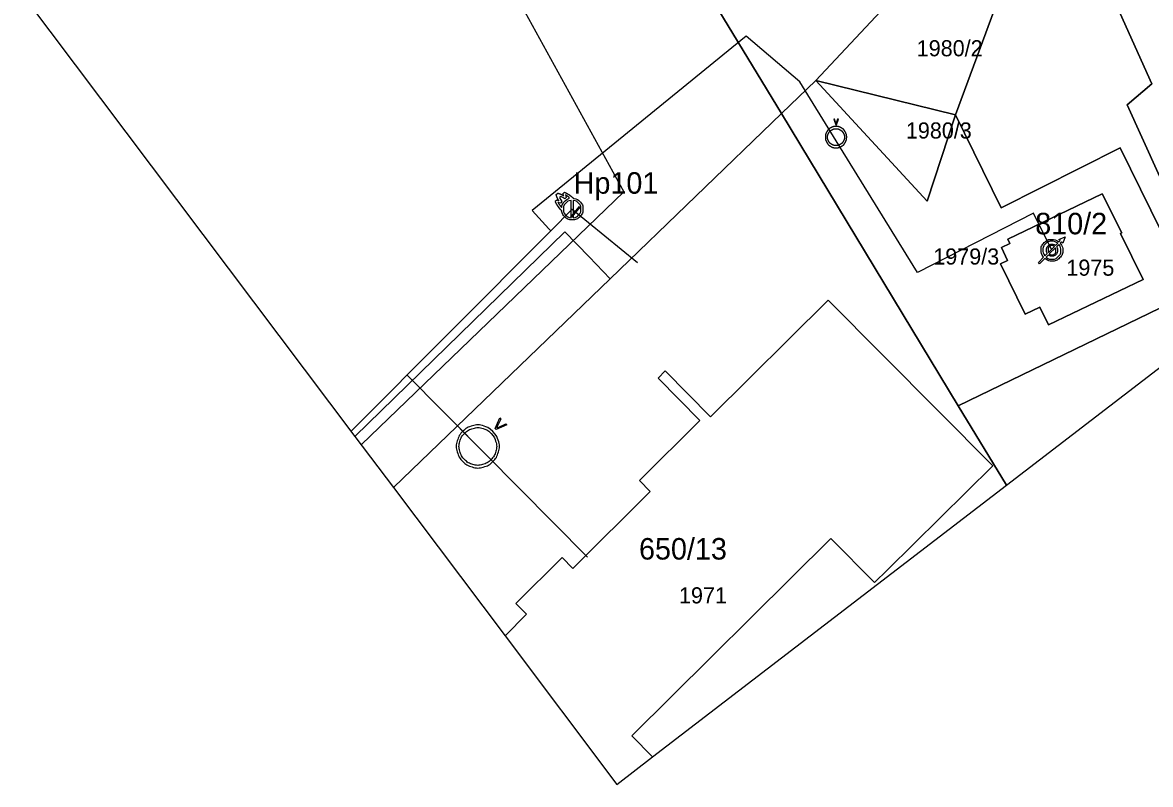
# Model space of a CAD drawing. Extents: x -570698 to -570232, y -1086952 to -1086596.
# Drawn here: x -570538 to -570433, y -1086951.6 to -1086880.7 of the extents above; entities that cross this region are included whole.
import ezdxf

# ---------------------------------------------------------------- set-up
doc = ezdxf.new("R2010")
doc.units = 0
for name, color, linetype in [('Adresní místo-text', 7, 'Continuous'), ('Armatura vodovodní', 7, 'Continuous'), ('Default', 7, 'Continuous'), ('Hydrant', 7, 'Continuous'), ('Kanalizační stoka', 7, 'Continuous'), ('Odběrné místo', 7, 'Continuous'), ('Označení hydrantu', 7, 'Continuous'), ('Parcela-polygon', 7, 'Continuous'), ('Parcela-text', 7, 'Continuous'), ('Vodovodní přípojka', 7, 'Continuous'), ('Vodovodní řad', 7, 'Continuous'), ('Vodovodní šachta', 7, 'Continuous')]:
    doc.layers.add(name, color=color, linetype=linetype)

msp = doc.modelspace()

# ---------------------------------------------------------------- linework, layer by layer
at = {"layer": 'Armatura vodovodní'}
msp.add_lwpolyline([(-570486.13, -1086897.88), (-570486.92, -1086898.84), (-570486.99, -1086898.79), (-570486.19, -1086897.83), (-570486.13, -1086897.88)], dxfattribs=at)
at = {"layer": 'Default'}
for points, degree in [([(-570463.17, -1086890.89), (-570463.26, -1086891.05), (-570463.3, -1086891.22), (-570463.3, -1086891.39)], 2), ([(-570462.8, -1086890.53), (-570462.96, -1086890.61), (-570463.08, -1086890.73), (-570463.17, -1086890.89)], 2), ([(-570463.1, -1086891.39), (-570463.1, -1086891.26), (-570463.06, -1086891.13), (-570462.99, -1086891)], 2), ([(-570462.99, -1086891), (-570462.92, -1086890.88), (-570462.82, -1086890.78), (-570462.7, -1086890.71)], 2), ([(-570462.32, -1086890.4), (-570462.48, -1086890.4), (-570462.64, -1086890.44), (-570462.8, -1086890.53)], 2), ([(-570462.7, -1086890.71), (-570462.57, -1086890.64), (-570462.45, -1086890.61), (-570462.32, -1086890.61)], 2), ([(-570462.31, -1086890.13), (-570462.31, -1086890.11), (-570462.31, -1086890.1), (-570462.32, -1086890.09)], 2), ([(-570461.83, -1086890.53), (-570461.99, -1086890.44), (-570462.15, -1086890.4), (-570462.32, -1086890.4)], 2), ([(-570462.32, -1086890.61), (-570462.18, -1086890.61), (-570462.06, -1086890.64), (-570461.93, -1086890.71)], 2), ([(-570462.29, -1086890.09), (-570462.3, -1086890.1), (-570462.3, -1086890.11), (-570462.31, -1086890.13)], 2), ([(-570461.93, -1086890.71), (-570461.81, -1086890.78), (-570461.71, -1086890.88), (-570461.64, -1086891)], 2), ([(-570461.46, -1086890.89), (-570461.55, -1086890.73), (-570461.67, -1086890.61), (-570461.83, -1086890.53)], 2), ([(-570461.64, -1086891), (-570461.57, -1086891.13), (-570461.53, -1086891.26), (-570461.53, -1086891.39)], 2), ([(-570461.32, -1086891.39), (-570461.32, -1086891.22), (-570461.37, -1086891.05), (-570461.46, -1086890.89)], 2), ([(-570463.3, -1086891.39), (-570463.3, -1086891.56), (-570463.26, -1086891.73), (-570463.17, -1086891.88)], 2), ([(-570463.17, -1086891.88), (-570463.08, -1086892.04), (-570462.96, -1086892.16), (-570462.8, -1086892.25)], 2), ([(-570462.99, -1086891.78), (-570463.06, -1086891.66), (-570463.1, -1086891.53), (-570463.1, -1086891.39)], 2), ([(-570462.7, -1086892.07), (-570462.82, -1086892), (-570462.92, -1086891.9), (-570462.99, -1086891.78)], 2), ([(-570461.64, -1086891.78), (-570461.71, -1086891.9), (-570461.8, -1086892), (-570461.93, -1086892.07)], 2), ([(-570461.82, -1086892.25), (-570461.66, -1086892.16), (-570461.54, -1086892.04), (-570461.45, -1086891.88)], 2), ([(-570461.53, -1086891.39), (-570461.53, -1086891.53), (-570461.57, -1086891.66), (-570461.64, -1086891.78)], 2), ([(-570461.45, -1086891.88), (-570461.37, -1086891.73), (-570461.32, -1086891.56), (-570461.32, -1086891.39)], 2), ([(-570462.8, -1086892.25), (-570462.65, -1086892.34), (-570462.48, -1086892.38), (-570462.32, -1086892.38)], 2), ([(-570462.32, -1086892.17), (-570462.45, -1086892.17), (-570462.58, -1086892.14), (-570462.7, -1086892.07)], 2), ([(-570461.93, -1086892.07), (-570462.05, -1086892.14), (-570462.18, -1086892.17), (-570462.32, -1086892.17)], 2), ([(-570462.32, -1086892.38), (-570462.14, -1086892.38), (-570461.98, -1086892.34), (-570461.82, -1086892.25)], 2), ([(-570488.11, -1086897.3), (-570488.28, -1086897.03), (-570488.36, -1086896.74)], 2), ([(-570488.21, -1086896.6), (-570487.93, -1086896.67), (-570487.65, -1086896.84)], 2), ([(-570487.56, -1086897.13), (-570487.81, -1086896.94), (-570488.1, -1086896.85), (-570488.01, -1086897.14), (-570487.82, -1086897.39)], 3), ([(-570486.73, -1086897.09), (-570486.41, -1086897.13), (-570486.16, -1086897.37), (-570485.87, -1086897.67), (-570485.87, -1086898.08), (-570485.87, -1086898.49), (-570486.16, -1086898.79), (-570486.45, -1086899.08), (-570486.87, -1086899.08), (-570487.28, -1086899.08), (-570487.57, -1086898.79), (-570487.82, -1086898.55), (-570487.86, -1086898.22)], 3), ([(-570486.96, -1086897.27), (-570487.24, -1086897.3), (-570487.45, -1086897.51), (-570487.69, -1086897.75), (-570487.68, -1086898.08), (-570487.68, -1086898.42), (-570487.44, -1086898.66), (-570487.24, -1086898.86), (-570486.96, -1086898.89)], 3), ([(-570487.59, -1086896.51), (-570487.33, -1086896.63), (-570487.1, -1086896.78)], 2), ([(-570487.51, -1086897.31), (-570487.29, -1086897.13), (-570487.02, -1086897.09), (-570487.24, -1086896.91), (-570487.48, -1086896.77)], 3), ([(-570486.84, -1086896.99), (-570486.83, -1086897), (-570486.73, -1086897.09)], 2), ([(-570486.77, -1086898.89), (-570486.5, -1086898.86), (-570486.3, -1086898.65), (-570486.06, -1086898.42), (-570486.06, -1086898.08), (-570486.06, -1086897.74), (-570486.3, -1086897.51), (-570486.5, -1086897.3), (-570486.78, -1086897.27)], 3), ([(-570488.17, -1086897.85), (-570488.32, -1086897.63), (-570488.44, -1086897.36)], 2), ([(-570488.19, -1086897.47), (-570488.04, -1086897.72), (-570487.86, -1086897.93)], 2), ([(-570487.86, -1086898.26), (-570487.86, -1086898.24), (-570487.87, -1086898.22), (-570487.97, -1086898.1), (-570488.05, -1086898.01)], 3), ([(-570487.86, -1086897.93), (-570487.82, -1086897.66), (-570487.64, -1086897.44)], 2), ([(-570442.99, -1086902.56), (-570443.23, -1086902.29), (-570443.23, -1086901.91), (-570443.23, -1086901.49), (-570442.93, -1086901.2), (-570442.64, -1086900.9), (-570442.22, -1086900.9), (-570441.84, -1086900.9), (-570441.57, -1086901.14)], 3), ([(-570441.68, -1086901.26), (-570441.91, -1086901.07), (-570442.22, -1086901.07), (-570442.57, -1086901.07), (-570442.81, -1086901.32), (-570443.06, -1086901.56), (-570443.06, -1086901.91), (-570443.06, -1086902.22), (-570442.87, -1086902.44)], 3), ([(-570441.46, -1086901.25), (-570441.21, -1086901.53), (-570441.21, -1086901.91), (-570441.21, -1086902.33), (-570441.5, -1086902.62), (-570441.8, -1086902.92), (-570442.22, -1086902.92), (-570442.6, -1086902.92), (-570442.88, -1086902.67)], 3), ([(-570442.76, -1086902.55), (-570442.53, -1086902.75), (-570442.22, -1086902.75), (-570441.87, -1086902.75), (-570441.62, -1086902.5), (-570441.38, -1086902.26), (-570441.38, -1086901.91), (-570441.38, -1086901.6), (-570441.58, -1086901.37)], 3), ([(-570442.65, -1086902.22), (-570442.65, -1086902.21), (-570442.66, -1086902.19), (-570442.72, -1086902.07), (-570442.72, -1086901.92), (-570442.72, -1086901.66), (-570442.58, -1086901.5), (-570442.44, -1086901.35), (-570442.21, -1086901.35), (-570442.06, -1086901.35), (-570441.94, -1086901.42), (-570441.91, -1086901.44), (-570441.89, -1086901.46)], 3), ([(-570441.98, -1086901.56), (-570442, -1086901.54), (-570442.02, -1086901.53), (-570442.1, -1086901.48), (-570442.21, -1086901.48), (-570442.36, -1086901.48), (-570442.47, -1086901.58), (-570442.58, -1086901.68), (-570442.58, -1086901.93), (-570442.58, -1086902.04), (-570442.54, -1086902.12)], 3), ([(-570441.79, -1086901.58), (-570441.77, -1086901.6), (-570441.76, -1086901.62), (-570441.7, -1086901.75), (-570441.7, -1086901.91), (-570441.7, -1086902.07), (-570441.76, -1086902.2), (-570441.83, -1086902.33), (-570441.95, -1086902.4), (-570442.07, -1086902.47), (-570442.21, -1086902.47), (-570442.36, -1086902.47), (-570442.48, -1086902.39), (-570442.52, -1086902.37), (-570442.55, -1086902.34)], 3), ([(-570442.46, -1086902.25), (-570442.36, -1086902.34), (-570442.21, -1086902.34), (-570442.05, -1086902.34), (-570441.95, -1086902.23), (-570441.84, -1086902.12), (-570441.84, -1086901.91), (-570441.84, -1086901.78), (-570441.89, -1086901.68), (-570441.89, -1086901.68), (-570441.89, -1086901.68)], 3), ([(-570494.25, -1086918.76), (-570493.89, -1086919.12), (-570493.74, -1086919.63), (-570493.59, -1086920.15), (-570493.74, -1086920.67), (-570493.89, -1086921.2), (-570494.26, -1086921.57), (-570494.62, -1086921.93), (-570495.14, -1086922.07), (-570495.66, -1086922.22), (-570496.17, -1086922.07), (-570496.69, -1086921.92), (-570497.06, -1086921.55), (-570497.41, -1086921.19), (-570497.56, -1086920.67), (-570497.71, -1086920.15), (-570497.56, -1086919.63), (-570497.41, -1086919.12), (-570497.04, -1086918.75), (-570496.68, -1086918.39), (-570496.15, -1086918.24), (-570495.63, -1086918.09), (-570495.11, -1086918.25), (-570494.6, -1086918.41), (-570494.25, -1086918.76)], 3), ([(-570494.42, -1086918.94), (-570494.73, -1086918.63), (-570495.18, -1086918.49), (-570495.63, -1086918.35), (-570496.09, -1086918.48), (-570496.55, -1086918.61), (-570496.87, -1086918.93), (-570497.19, -1086919.25), (-570497.32, -1086919.7), (-570497.45, -1086920.15), (-570497.32, -1086920.6), (-570497.2, -1086921.06), (-570496.88, -1086921.38), (-570496.56, -1086921.7), (-570496.11, -1086921.83), (-570495.66, -1086921.96), (-570495.2, -1086921.83), (-570494.75, -1086921.71), (-570494.43, -1086921.39), (-570494.11, -1086921.07), (-570493.98, -1086920.61), (-570493.85, -1086920.15), (-570493.98, -1086919.7), (-570494.11, -1086919.25), (-570494.42, -1086918.94)], 3), ([(-570493.84, -1086918.31), (-570493.88, -1086918.4), (-570493.92, -1086918.46), (-570493.84, -1086918.42), (-570493.76, -1086918.39)], 3)]:
    msp.add_open_spline(points, degree=degree, dxfattribs=at)
at = {"layer": 'Hydrant'}
for points in [[(-570488.44, -1086897.36), (-570488.3, -1086897.22), (-570488.11, -1086897.3)], [(-570488.36, -1086896.74), (-570488.21, -1086896.6)], [(-570487.65, -1086896.84), (-570487.73, -1086896.66), (-570487.59, -1086896.51)], [(-570487.48, -1086896.77), (-570487.42, -1086896.99), (-570487.56, -1086897.13)], [(-570487.1, -1086896.78), (-570486.94, -1086896.91), (-570486.84, -1086896.99)], [(-570486.96, -1086898.89), (-570486.96, -1086897.27)], [(-570486.78, -1086897.27), (-570486.77, -1086898.89)], [(-570487.82, -1086897.39), (-570487.96, -1086897.54), (-570488.19, -1086897.47)], [(-570488.05, -1086898.01), (-570488.17, -1086897.85)], [(-570487.86, -1086898.22), (-570487.86, -1086898.26)], [(-570487.64, -1086897.44), (-570487.51, -1086897.31)]]:
    msp.add_lwpolyline(points, dxfattribs=at)
at = {"layer": 'Kanalizační stoka'}
msp.add_lwpolyline([(-570457.86, -1086836.16), (-570493.65, -1086875.35), (-570482.06, -1086896.49), (-570506.5, -1086920.01)], dxfattribs=at)
at = {"layer": 'Odběrné místo'}
for points in [[(-570441.89, -1086901.46), (-570441.68, -1086901.26)], [(-570441.58, -1086901.37), (-570441.79, -1086901.58)], [(-570441.57, -1086901.14), (-570441.44, -1086901.01)], [(-570441.44, -1086901.01), (-570441.56, -1086900.9), (-570440.97, -1086900.66), (-570441.19, -1086901.25), (-570441.33, -1086901.12), (-570441.46, -1086901.25)], [(-570442.87, -1086902.44), (-570442.65, -1086902.22)], [(-570442.55, -1086902.34), (-570442.76, -1086902.55)], [(-570442.54, -1086902.12), (-570441.98, -1086901.56)], [(-570441.89, -1086901.68), (-570442.46, -1086902.25)], [(-570442.88, -1086902.67), (-570443.37, -1086903.16), (-570443.47, -1086903.05), (-570442.99, -1086902.56)]]:
    msp.add_lwpolyline(points, dxfattribs=at)
at = {"layer": 'Parcela-polygon'}
for p, q in [((-570538.02, -1086878.14), (-570507.09, -1086919.23)), ((-570446.46, -1086923.76), (-570427.79, -1086909.43)), ((-570507.09, -1086919.23), (-570503.51, -1086923.98)), ((-570503.51, -1086923.98), (-570493.12, -1086937.77)), ((-570479.39, -1086949.04), (-570446.46, -1086923.76))]:
    msp.add_line(p, q, dxfattribs=at)
for points in [[(-570314.47, -1086822.42), (-570326.4, -1086786.46), (-570358.49, -1086797.03), (-570369.36, -1086800.59), (-570374.8, -1086803.82), (-570380.97, -1086807.48), (-570374.82, -1086826.12), (-570380.47, -1086828.04), (-570398.24, -1086834.1), (-570397.51, -1086836.02), (-570406.58, -1086839.09), (-570441.99, -1086865.7), (-570438.81, -1086873.31), (-570432.93, -1086886.42), (-570435.2, -1086888.38), (-570429.44, -1086901.1), (-570427.79, -1086909.43)], [(-570507.09, -1086919.23), (-570487.55, -1086900.19), (-570485.3, -1086902.53), (-570483.34, -1086904.56), (-570467.38, -1086889.2), (-570492.56, -1086847.83), (-570501.11, -1086855.03), (-570507, -1086859.73), (-570511.23, -1086862.75), (-570515.08, -1086865.32), (-570518.55, -1086867.44), (-570522.04, -1086869.52), (-570526.69, -1086872.16), (-570538.02, -1086878.14)], [(-570427.79, -1086909.43), (-570429.44, -1086901.1), (-570435.2, -1086888.38), (-570432.93, -1086886.42), (-570438.81, -1086873.31), (-570441.99, -1086865.7), (-570442.31, -1086864.93), (-570447.84, -1086880.26), (-570451.19, -1086889.31), (-570446.95, -1086897.96), (-570435.85, -1086892.39), (-570429.23, -1086905.88), (-570450.94, -1086916.37), (-570446.46, -1086923.76)], [(-570446.46, -1086923.76), (-570450.94, -1086916.37), (-570467.38, -1086889.2), (-570483.34, -1086904.56), (-570503.51, -1086923.98)], [(-570503.51, -1086923.98), (-570483.34, -1086904.56), (-570485.3, -1086902.53), (-570487.55, -1086900.19), (-570507.09, -1086919.23)], [(-570493.12, -1086937.77), (-570491.11, -1086935.77), (-570492.11, -1086934.77), (-570487.81, -1086930.49), (-570486.8, -1086931.5), (-570479.6, -1086924.35), (-570480.6, -1086923.34), (-570474.98, -1086917.75), (-570478.88, -1086913.81), (-570478.2, -1086913.14), (-570473.98, -1086917.41), (-570463.03, -1086906.56), (-570447.71, -1086921.95), (-570457.53, -1086931.62), (-570458.74, -1086932.81), (-570462.79, -1086928.72), (-570481.33, -1086947.08), (-570479.39, -1086949.04)], [(-570479.39, -1086949.04), (-570481.33, -1086947.08), (-570462.79, -1086928.72), (-570458.74, -1086932.81), (-570457.53, -1086931.62), (-570447.71, -1086921.95), (-570463.03, -1086906.56), (-570473.98, -1086917.41), (-570478.2, -1086913.14), (-570478.88, -1086913.81), (-570474.98, -1086917.75), (-570480.6, -1086923.34), (-570479.6, -1086924.35), (-570486.8, -1086931.5), (-570487.81, -1086930.49), (-570492.11, -1086934.77), (-570491.11, -1086935.77), (-570493.12, -1086937.77)], [(-570493.12, -1086937.77), (-570482.71, -1086951.6), (-570479.39, -1086949.04)]]:
    msp.add_lwpolyline(points, dxfattribs=at)
for points in [[(-570466.87, -1086826.17), (-570492.56, -1086847.83), (-570467.38, -1086889.2), (-570464.2, -1086886.11), (-570451.2, -1086872.23), (-570447.36, -1086868.05), (-570442.53, -1086861.49), (-570441.86, -1086860.44), (-570449.02, -1086853.9)], [(-570464.2, -1086886.11), (-570451.19, -1086889.31), (-570447.84, -1086880.26), (-570442.31, -1086864.93), (-570441.01, -1086861.21), (-570441.86, -1086860.44), (-570442.53, -1086861.49), (-570447.36, -1086868.05), (-570451.2, -1086872.23)], [(-570467.38, -1086889.2), (-570450.94, -1086916.37), (-570429.23, -1086905.88), (-570435.85, -1086892.39), (-570446.95, -1086897.96), (-570451.19, -1086889.31), (-570453.82, -1086897.33), (-570464.2, -1086886.11)], [(-570451.19, -1086889.31), (-570464.2, -1086886.11), (-570453.82, -1086897.33)], [(-570437.53, -1086896.65), (-570435.72, -1086900.3), (-570435.84, -1086900.36), (-570433.72, -1086904.64), (-570442.53, -1086908.84), (-570443.35, -1086907.19), (-570444.72, -1086907.87), (-570447.01, -1086903.17), (-570446.34, -1086902.85), (-570446.92, -1086901.65), (-570446.14, -1086901.28), (-570446.33, -1086900.88)], [(-570437.53, -1086896.65), (-570446.33, -1086900.88), (-570446.14, -1086901.28), (-570446.92, -1086901.65), (-570446.34, -1086902.85), (-570447.01, -1086903.17), (-570444.72, -1086907.87), (-570443.35, -1086907.19), (-570442.53, -1086908.84), (-570433.72, -1086904.64), (-570435.84, -1086900.36), (-570435.72, -1086900.3)]]:
    msp.add_lwpolyline(points, close=True, dxfattribs=at)
at = {"layer": 'Vodovodní přípojka'}
msp.add_line((-570498.17, -1086917.61), (-570485.44, -1086930.45), dxfattribs=at)
for points in [[(-570442.22, -1086901.91), (-570443.93, -1086898.45), (-570454.72, -1086903.98), (-570462.31, -1086891.73), (-570465.68, -1086886.23), (-570470.69, -1086881.99), (-570490.58, -1086898.22), (-570489.03, -1086899.92), (-570488.87, -1086900.09)], [(-570486.87, -1086898.08), (-570480.8, -1086903.04)], [(-570502.23, -1086913.52), (-570495.65, -1086920.16)]]:
    msp.add_lwpolyline(points, dxfattribs=at)
at = {"layer": 'Vodovodní řad'}
msp.add_lwpolyline([(-570507.44, -1086918.75), (-570488.87, -1086900.09), (-570486.87, -1086898.08)], dxfattribs=at)
at = {"layer": 'Vodovodní šachta'}
for points in [[(-570462.32, -1086890.09), (-570462.44, -1086889.73), (-570462.53, -1086889.73), (-570462.34, -1086890.23)], [(-570462.34, -1086890.23), (-570462.27, -1086890.23), (-570462.07, -1086889.73), (-570462.16, -1086889.73), (-570462.29, -1086890.09)], [(-570494.04, -1086918.49), (-570493.6, -1086917.51), (-570493.5, -1086917.61), (-570493.84, -1086918.31)], [(-570493.76, -1086918.39), (-570493.05, -1086918.07), (-570492.96, -1086918.16), (-570493.95, -1086918.59), (-570494.04, -1086918.49)]]:
    msp.add_lwpolyline(points, dxfattribs=at)

# ---------------------------------------------------------------- texts
at = {"layer": 'Adresní místo-text'}
for s, p in [('810/2', (-570443.77, -1086900.43)), ('650/13', (-570480.65, -1086930.68))]:
    msp.add_text(s, height=2, dxfattribs=at).set_placement(p)
at = {"layer": 'Označení hydrantu'}
msp.add_text('Hp101', height=2, dxfattribs=at).set_placement((-570486.73, -1086896.65))
at = {"layer": 'Parcela-text'}
for s, p in [('1980/2', (-570454.8, -1086883.87)), ('1980/3', (-570455.81, -1086891.52)), ('1979/3', (-570453.26, -1086903.24)), ('1975', (-570440.87, -1086904.28)), ('1971', (-570476.93, -1086934.76))]:
    msp.add_text(s, height=1.5, dxfattribs=at).set_placement(p)

doc.saveas('drawing.dxf')
